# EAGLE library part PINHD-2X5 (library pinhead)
PIN HEADER
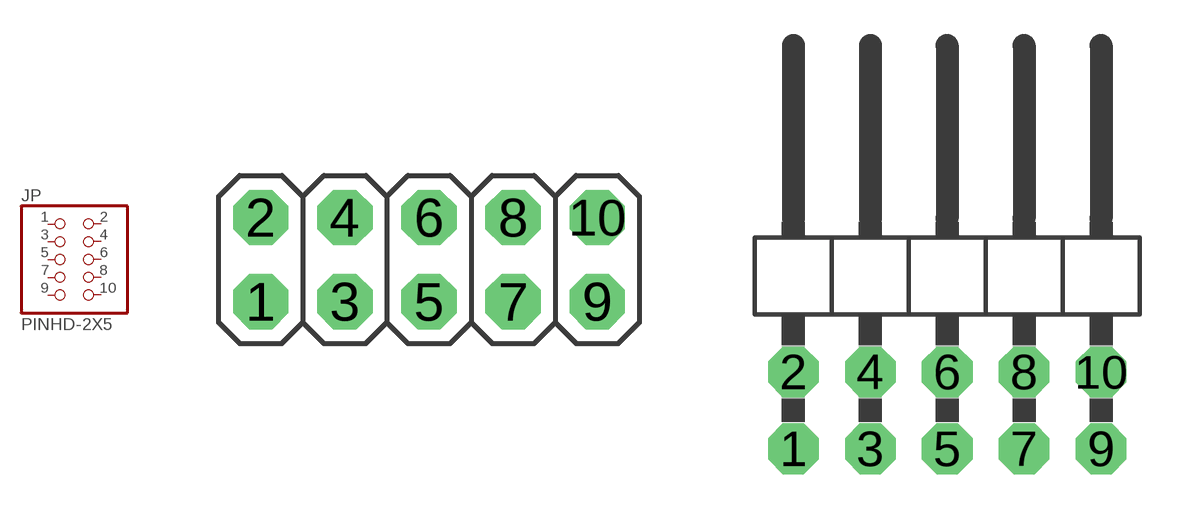
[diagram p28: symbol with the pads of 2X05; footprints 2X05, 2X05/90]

Designator prefix JP

## PINHD-2X5  [2X05]
1  1  pas
2  2  pas
3  3  pas
4  4  pas
5  5  pas
6  6  pas
7  7  pas
8  8  pas
9  9  pas
10  10  pas

## PINHD-2X5/90  [2X05/90]
Pads as for 2X05

## Footprint 2X05 (pad centres in mm)
PIN HEADER
drill 1.016 pad 1.67 octagon: 1 -5.08,-1.27; 2 -5.08,1.27; 3 -2.54,-1.27; 4 -2.54,1.27; 5 0,-1.27; 6 0,1.27; 7 2.54,-1.27; 8 2.54,1.27; 9 5.08,-1.27; 10 5.08,1.27

## Footprint 2X05/90 (pad centres in mm)
PIN HEADER
drill 1.016 pad 1.67 octagon: 1 -5.08,-6.35; 2 -5.08,-3.81; 3 -2.54,-6.35; 4 -2.54,-3.81; 5 0,-6.35; 6 0,-3.81; 7 2.54,-6.35; 8 2.54,-3.81; 9 5.08,-6.35; 10 5.08,-3.81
